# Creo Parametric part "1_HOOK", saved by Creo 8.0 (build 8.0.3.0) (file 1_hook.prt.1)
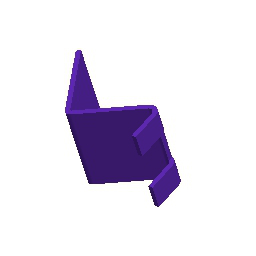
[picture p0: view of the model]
Units: millimeter Newton Second (mmNs); MM, TONNE, SECS

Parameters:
  SMT_DFLT_BEND_REL_LENGTH_TYPE = "Through All"

Other parameters: SMT_THICKNESS, SMT_PART_BEND_ALLOWANCE_FACTOR, SMT_DFLT_BEND_RADIUS, SMT_DFLT_BEND_ANGLE, SMT_DFLT_CRNR_REL_WIDTH, SMT_DFLT_CRNR_REL_DEPTH, SMT_DFLT_BEND_REL_WIDTH, SMT_DFLT_BEND_REL_DEPTH, SMT_DFLT_BEND_REL_LENGTH, SMT_DFLT_BEND_REL_ANGLE, SMT_GAP, SMT_DFLT_EDGE_TREA_WIDTH, SMT_DFLT_MITER_CUT_WIDTH, SMT_DFLT_MITER_CUT_OFFSET

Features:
  1. datum plane "DTM1"
  2. datum plane "DTM2"
  3. datum plane "DTM3"
  4. cut
  5. cut

Layers: 0_ALL_AXIS, 0_ALL_CSYS, 0_ALL_CURVES, 0_ALL_PLANES, 0_ALL_POINTS, 0_ALL_SURFS, HOOK

Surfaces: 21 plane, 5 cylinder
